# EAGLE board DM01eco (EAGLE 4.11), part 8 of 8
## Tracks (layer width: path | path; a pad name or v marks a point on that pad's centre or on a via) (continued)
N$57  (via drill 0.61) (continued)
  Route2 0.152: v266.06,171.45 v269.88,175.26
  Bottom 0.152: v269.88,175.26 268.61,176.53 268.61,177.16 B11.L2 | v266.06,171.45 266.06,170.18 v287.02,149.22 | v294.64,156.84 298.45,156.84 302.26,153.03 303.53,153.03 305.44,151.13 307.34,151.13 310.51,147.96 | 310.51,147.96 320.68,137.8 320.68,132.08 319.4,130.81 C07.D2 | 310.51,147.96 v311.15,148.59
N$58  (via drill 0.61)
  Top 0.152: v365.76,149.86 364.49,149.86 357.5,142.88 354.33,142.88 v348.62,137.16 | v299.72,206.38 296.55,203.2 291.46,208.28 288.29,208.28 281.94,201.93 276.86,201.93 271.78,196.85 271.78,194.31 B11.E2 | v317.5,184.15 317.5,184.78 318.13,185.42 320.68,185.42 321.94,186.69 B07.H2
  Route2 0.152: v306.07,160.66 306.07,161.93 320.68,176.53 320.68,185.42 321.94,186.69 B07.H2
  Route15 0.152: v299.72,206.38 318.13,187.96 318.13,186.06 316.87,184.78 v317.5,184.15
  Bottom 0.152: v365.76,149.86 382.27,133.35 382.27,130.81 C02.D2 | v348.62,137.16 344.81,133.35 339.73,138.43 332.74,138.43 329.56,141.61 327.02,141.61 325.75,142.88 321.31,142.88 315.6,148.59 313.69,148.59 310.51,151.77 310.51,154.31 311.79,155.58 306.7,160.66 v306.07,160.66
N$59  (via drill 0.61)
  Top 0.152: v266.06,184.15 267.97,186.06 267.97,189.87 B11.F2 | v297.81,153.03 304.8,160.02 304.8,161.29 307.98,164.47 307.98,170.18 321.94,184.15 323.21,182.88 321.94,181.61 B07.K2
  Route15 0.152: v266.06,184.15 266.06,182.88 295.91,153.03 v297.81,153.03 | C03.D2 369.57,130.81 369.57,133.35 365.12,137.8 365.12,139.06 358.14,146.05 353.06,146.05 346.71,152.4 346.71,154.31 346.07,154.94 346.07,159.39 342.9,162.56 342.9,163.19 332.74,173.36 332.74,174.62 331.47,175.9 330.2,175.9 326.39,179.71 323.21,179.71 322.58,180.34 B07.K2
N$60  (via drill 0.61)
  Route2 0.152: v298.45,168.28 300.36,168.28 303.53,165.1 304.8,166.37 305.44,166.37 311.15,172.09 311.15,172.72 314.96,176.53 316.23,176.53 v317.5,177.8
  Route15 0.152: B07.M2 322.58,173.99 322.58,170.81 333.38,160.02 333.38,154.31 337.19,150.5 341,150.5 346.71,144.78 346.71,143.51 356.24,133.98 356.24,131.44 356.87,130.81 C04.D2
  Bottom 0.152: v298.45,168.28 298.45,168.91 294.64,172.72 289.56,172.72 276.23,186.06 276.23,186.69 274.32,188.59 273.69,188.59 271.14,191.14 269.88,189.87 271.14,188.59 271.14,187.96 B11.H2 | v317.5,177.8 317.5,177.16 318.13,176.53 320.68,176.53 321.94,175.26 B07.M2
N$61  (via drill 0.61)
  Route2 0.152: v266.7,178.44 267.33,179.07 267.33,181.61 267.97,182.25 267.97,183.52 B11.J2 | v280.67,167 280.67,168.91 278.13,171.45 292.1,185.42 v297.18,185.42
  Route15 0.152: C05.D2 344.17,130.81 344.17,133.98 339.09,139.06 339.09,140.34 333.38,146.05 333.38,147.96 323.21,158.12 323.21,160.66 325.12,162.56 323.21,164.47 323.21,167 322.58,167.64 B07.P2 321.94,167.64 319.4,167.64 310.51,176.53 304.8,176.53 297.18,184.15 v297.18,185.42
  Bottom 0.152: v266.7,178.44 266.7,177.16 270.51,173.36 275.59,173.36 280.04,168.91 280.04,167.64 v280.67,167
N$62  (via drill 0.61)
  Top 0.152: v279.4,177.16 281.31,175.26 v295.91,189.87 | v334.64,142.24 333.38,140.97 333.38,135.89 332.11,134.62 332.11,130.81 C06.D2
  Route15 0.152: v334.64,142.24 334.64,144.15 332.74,146.05 332.74,147.96 322.58,158.12 322.58,161.29 B07.S2
  Bottom 0.152: v279.4,177.16 278.76,177.16 276.23,179.71 276.23,180.34 274.32,182.25 273.69,182.25 273.05,182.88 271.78,181.61 B11.K2 | v295.91,189.87 297.18,189.87 320.68,166.37 320.68,163.83 321.94,162.56 B07.S2
N$63  (via drill 0.61)
  Route2 0.152: v245.75,170.18 245.75,170.81 257.81,182.88 v258.44,182.88
  Route15 0.152: v258.44,182.88 259.71,182.88 263.52,179.07 | 263.52,179.07 264.8,179.07 267.33,176.53 269.88,176.53 271.14,175.26 B11.M2 | 263.52,179.07 300.99,141.61 304.17,141.61 312.42,133.35 309.88,130.81 306.7,130.81 C08.D2
  Bottom 0.152: v245.75,170.18 244.47,171.45 244.47,172.72 237.49,179.71 236.85,179.71 234.31,182.25 234.31,182.88 223.52,193.68 220.98,193.68 B15.E2
N$64  (via drill 0.61)
  Top 0.152: B06.J2 332.11,184.78 332.74,184.78 334.64,186.69 B06.H2
  Route2 0.152: v295.27,183.52 296.55,183.52 299.08,186.06 300.99,186.06 303.53,183.52 305.44,185.42 311.15,185.42 314.96,189.23 320.04,189.23 323.85,193.04 v323.85,193.68
  Route15 0.152: v323.85,193.68 325.75,193.68 328.93,190.5 329.56,190.5 330.83,189.23 333.38,189.23 334.64,187.96 B06.H2
  Bottom 0.152: v295.27,183.52 294.64,182.88 292.1,182.88 284.48,190.5 284.48,193.04 B10.E2
N$65  (via drill 0.61)
  Top 0.152: v290.83,191.14 287.65,187.96 284.48,187.96 B10.H2 | v315.6,166.37 323.21,166.37 v329.56,172.72
  Bottom 0.152: v290.83,191.14 290.83,190.5 314.96,166.37 v315.6,166.37 | v329.56,172.72 330.83,172.72 331.47,172.09 B06.N2 332.11,170.81 334.01,168.91 334.64,168.91 B06.P2
N$66  (via drill 0.61)
  Top 0.152: B23.V2 116.2,153.03 116.84,153.03 118.75,154.94 B23.U2 | v259.71,130.81 280.04,151.13 281.94,151.13 283.85,153.03 283.85,154.94 B10.U2
  Route2 0.152: v259.71,130.81 257.81,130.81 255.27,133.35 253.37,131.44 250.82,131.44 243.84,138.43 243.84,139.06 231.78,151.13 226.69,151.13 226.06,151.77 v218.44,144.15 | v205.1,149.86 180.97,149.86 174.62,143.51 158.75,143.51 156.84,141.61 155.57,141.61 148.59,134.62 139.7,134.62 138.43,135.89 v137.79,135.25
  Bottom 0.152: v218.44,144.15 217.81,144.15 215.9,146.05 214.63,146.05 214,146.69 208.28,146.69 v205.1,149.86 | v137.79,135.25 137.16,135.25 135.25,133.35 116.2,152.4 B23.V2
N$67  (via drill 0.61)
  Top 0.152: v301.62,147.32 306.07,151.77 B08.V2 306.7,153.03 308.61,154.94 309.25,154.94 B08.U2
  Bottom 0.152: v301.62,147.32 287.65,161.29 284.48,161.29 B10.S2
N$68  (via drill 0.61)
  Top 0.152: v287.65,169.55 287.02,168.91 284.48,168.91 B10.P2 | v294,161.93 302.26,170.18 305.44,170.18 306.07,170.81 B08.N2
  Bottom 0.152: v287.65,169.55 287.65,168.28 v294,161.93 | B08.P2 309.25,168.91 308.61,168.91 306.7,170.81 B08.N2
N$69
  Top 0.152: B08.H2 309.25,186.69 308.61,186.69 306.7,184.78 B08.J2
  Route2 0.152: B10.M2 284.48,175.26 287.65,175.26 290.19,177.8 291.46,177.8 292.74,179.07 297.18,179.07 299.08,180.97 300.36,180.97 302.26,182.88 305.44,182.88 306.07,183.52 B08.J2
N$70  (via drill 0.61)
  Top 0.152: v323.21,144.78 324.49,144.78 331.47,151.77 B06.V2 332.11,153.03 334.01,154.94 334.64,154.94 B06.U2
  Bottom 0.152: v323.21,144.78 287.65,180.34 284.48,180.34 B10.K2
N$71  (via drill 0.61)
  Top 0.152: v245.75,166.37 247.01,166.37 263.52,182.88 272.42,182.88 273.69,181.61 274.32,182.25 275.59,180.97 274.32,179.71 273.69,179.71 272.42,178.44 272.42,175.9 273.69,174.62 272.42,173.36 269.88,173.36 268.61,172.09 B11.N2
  Route2 0.152: v223.52,192.41 222.88,192.41 220.98,190.5 220.98,187.96 B15.H2 | v300.36,134.62 296.55,130.81 294,130.81 C09.D2
  Route15 0.152: v300.36,134.62 299.72,133.98 285.75,147.96 285.75,148.59 285.12,149.22 285.12,151.13 269.24,167 269.24,170.18 268.61,170.81 B11.N2
  Bottom 0.152: v223.52,192.41 222.88,192.41 220.98,190.5 245.11,166.37 v245.75,166.37
N$72  (via drill 0.61)
  Top 0.152: v252.73,153.67 253.37,153.67 258.44,158.75 258.44,159.39 262.25,163.19 262.89,163.19 267.33,167.64 267.33,168.91 v267.97,169.55
  Route2 0.152: v295.91,142.24 284.48,130.81 281.31,130.81 C10.D2
  Bottom 0.152: v252.73,153.67 251.46,153.67 234.95,170.18 234.95,170.81 226.69,179.07 226.06,179.07 224.79,180.34 220.98,180.34 B15.K2 | v267.97,169.55 270.51,169.55 271.14,168.91 B11.P2 271.78,167.64 272.42,167 272.42,164.47 286.38,150.5 287.02,150.5 295.27,142.24 v295.91,142.24
N$73  (via drill 0.61)
  Top 0.152: v226.69,177.8 223.52,174.62 220.98,174.62 B15.M2 | v272.42,135.89 271.78,135.89 269.88,133.98 269.88,132.08 268.61,130.81 C11.D2 | v274.32,160.66 275.59,160.66 277.5,158.75 v264.16,145.41
  Route15 0.152: v274.32,160.66 274.32,161.29 271.14,164.47 268.61,164.47 B11.R2
  Bottom 0.152: v226.69,177.8 252.09,152.4 253.37,152.4 254.63,151.13 257.18,151.13 263.52,144.78 | 263.52,144.78 v272.42,135.89 | 263.52,144.78 v264.16,145.41
N$74  (via drill 0.61)
  Top 0.152: v254,136.53 254,139.06 254.63,139.7 254.63,142.24 256.54,144.15 | 256.54,144.15 269.88,157.48 269.88,160.02 271.14,161.29 B11.S2 | 256.54,144.15 v255.27,145.41
  Route2 0.152: v227.97,171.45 227.33,170.81 226.06,170.81 224.16,168.91 220.98,168.91 B15.P2
  Bottom 0.152: v254,136.53 254,135.89 255.27,134.62 255.27,130.81 C12.D2 | v227.97,171.45 227.97,170.81 235.59,163.19 236.22,163.19 238.12,161.29 238.12,160.66 248.28,150.5 250.19,150.5 v255.27,145.41
N$75  (via drill 0.61)
  Top 0.152: v249.56,134.62 245.75,130.81 243.21,130.81 C13.D2 | v223.52,163.19 221.62,163.19 220.98,162.56 B15.S2 | v261.62,156.84 257.81,156.84 250.82,149.86 247.01,149.86 v243.21,146.05
  Bottom 0.152: v249.56,134.62 248.28,134.62 236.22,146.69 | 236.22,146.69 232.41,150.5 232.41,153.67 223.52,162.56 v223.52,163.19 | v261.62,156.84 262.25,156.21 264.16,158.12 267.97,158.12 B11.T2 | v243.21,146.05 240.66,146.05 240.03,146.69 236.22,146.69
N$76  (via drill 0.61)
  Top 0.152: v256.54,139.7 267.97,151.13 269.24,151.13 271.14,153.03 271.14,154.94 B11.U2 | v244.47,152.4 244.47,151.77 243.84,151.13 241.3,151.13 v232.41,142.24
  Route2 0.152: v232.41,142.24 231.78,141.61 231.78,135.89 230.5,134.62 230.5,130.81 C14.D2
  Bottom 0.152: v232.41,142.24 231.78,142.24 223.52,150.5 222.88,150.5 221.62,151.77 221.62,154.31 220.98,154.94 B15.U2 | v256.54,139.7 256.54,140.34 v244.47,152.4
N$77  (via drill 0.61)
  Top 0.152: 224.79,141.61 225.43,141.61 233.68,149.86 v233.68,150.5 | 224.79,141.61 223.52,141.61 222.25,140.34 222.25,139.06 220.34,137.16 222.25,135.25 222.25,132.72 220.34,130.81 217.81,130.81 C15.D2 | v241.3,147.96 241.94,147.96 254,160.02 255.27,160.02 v255.91,160.66 | v100.97,203.84 93.98,196.85 93.98,194.31 B25.E2 | v130.18,168.28 v130.18,162.56 | v150.5,141.61 156.84,141.61 165.1,149.86 166.37,149.86 168.28,151.77 170.81,151.77 175.9,146.69 186.06,156.84 186.69,156.84 195.58,165.74 v196.22,165.74 | v224.79,140.34 224.79,141.61
  Route2 0.152: v233.68,150.5 238.76,145.41 v241.3,147.96
  Route15 0.152: v196.22,165.74 195.58,165.1 207.01,153.67 207.01,152.4 209.55,149.86 210.82,149.86 215.26,145.41 219.71,145.41 v224.79,140.34
  Bottom 0.152: v255.91,160.66 256.54,160.66 263.52,153.67 267.33,153.67 267.97,153.03 B11.V2 | v100.97,203.84 100.97,202.56 108.58,194.94 108.58,194.31 130.18,172.72 v130.18,168.28 | v130.18,162.56 130.18,160.66 139.7,151.13 140.97,151.13 v150.5,141.61
N$78  (via drill 0.61)
  Top 0.152: B25.H2 93.98,187.96 97.16,187.96 102.23,193.04 102.23,195.58 102.87,196.22 B24.D2 | v170.18,166.37 167.64,163.83 162.56,163.83 161.93,163.19 161.93,162.56 160.02,160.66 159.38,160.66 158.12,159.39 158.12,156.84 159.38,155.58 154.94,151.13 151.13,151.13 143.51,143.51 142.24,143.51 138.43,147.32 v134.62,143.51
  Route15 0.152: v170.18,166.37 170.81,165.74 170.81,164.47 194.31,140.97 196.85,140.97 204.47,133.35 204.47,130.81 C16.D2 | v134.62,143.51 94.61,183.52 94.61,186.06 93.98,186.69 B25.H2
N$79  (via drill 0.61)
  Top 0.152: B25.K2 93.98,181.61 97.16,181.61 104.78,189.23 104.78,191.77 106.05,193.04 B24.E2 | v175.9,122.56 175.9,123.19 179.71,127 180.34,127 181.61,128.27 182.25,128.27 183.51,129.54 187.96,125.09 189.87,125.09 191.77,127 191.77,129.54 C17.D2
  Route15 0.152: v175.9,122.56 175.9,123.83 173.99,125.73 173.35,125.73 172.09,127 172.09,128.27 161.29,139.06 161.29,140.34 160.02,141.61 160.02,142.88 155.57,147.32 155.57,148.59 152.4,151.77 152.4,154.31 153.67,155.58 148.59,160.66 142.24,160.66 110.49,192.41 107.31,192.41 106.68,193.04 B24.E2
N$80  (via drill 0.61)
  Top 0.152: B25.M2 93.98,175.26 93.98,176.53 94.61,177.16 94.61,178.44 105.41,189.23 105.41,190.5 107.95,193.04 107.95,194.94 106.68,196.22 104.78,194.31 104.78,192.41 103.5,191.14 B24.F2 | v152.4,160.02 151.76,160.02 v144.15,152.4
  Route15 0.152: v144.15,152.4 120.65,175.9 118.75,175.9 117.47,177.16 117.47,179.07 110.49,186.06 105.41,186.06 104.78,186.69 104.78,188.59 103.5,189.87 B24.F2
  Bottom 0.152: v152.4,160.02 155.57,160.02 161.93,153.67 161.93,153.03 173.99,140.97 173.99,139.06 179.07,133.98 179.07,130.81 C18.D2
N$81  (via drill 0.61)
  Top 0.152: v109.86,181.61 97.16,168.91 93.98,168.91 B25.P2
  Route15 0.152: v109.86,181.61 109.86,180.97 147.96,142.88 150.5,142.88 162.56,130.81 166.37,130.81 C19.D2
  Bottom 0.152: v109.86,181.61 109.22,181.61 107.31,183.52 107.31,184.15 107.95,184.78 106.05,186.69 B24.H2
N$82  (via drill 0.61)
  Top 0.152: v109.22,187.33 108.58,187.33 107.31,186.06 104.78,186.06 103.5,184.78 B24.J2 | v106.05,163.83 106.05,164.47 v118.75,177.16
  Route2 0.152: v106.05,163.83 99.06,163.83 97.16,161.93 93.98,161.93 B25.S2
  Bottom 0.152: 118.75,177.8 v109.22,187.33 | 118.75,177.8 142.88,153.67 142.88,152.4 155.57,139.7 155.57,138.43 156.84,137.16 154.31,134.62 154.31,130.81 C20.D2 | v118.75,177.16 118.75,177.8
N$83
  Route2 0.152: B25.U2 93.34,156.21 93.34,160.02 88.27,165.1 89.53,166.37 94.61,166.37 104.78,176.53 104.78,179.07 106.05,180.34 B24.K2
  Bottom 0.152: C21.D2 140.97,130.81 140.97,133.98 135.89,139.06 135.89,147.32 129.54,153.67 129.54,154.94 111.12,173.36 111.12,173.99 109.22,175.9 108.58,175.9 107.31,177.16 107.31,179.71 106.68,180.34 B24.K2
N$84  (via drill 0.61)
  Top 0.152: v133.35,143.51 130.18,140.34 130.18,135.25 121.92,127 123.83,125.09 126.36,125.09 128.27,127 128.27,129.54 C22.D2
  Bottom 0.152: 99.06,179.07 102.23,179.07 102.87,178.44 B24.L2 | 99.06,179.07 98.42,179.07 84.45,193.04 81.28,193.04 B26.E2 | v133.35,143.51 133.35,144.78 99.06,179.07
N$85  (via drill 0.61)
  Top 0.152: v92.08,196.22 92.08,195.58 87,190.5 85.09,192.41 83.19,192.41 81.28,190.5 81.28,187.96 B26.H2 | v100.97,170.18 100.97,171.45 102.23,172.72 104.78,172.72 106.05,173.99 B24.M2
  Route2 0.152: v121.28,139.7 116.2,134.62 116.2,130.81 C23.D2
  Bottom 0.152: v92.08,196.22 90.81,194.94 90.81,194.31 95.25,189.87 95.25,189.23 102.87,181.61 103.5,181.61 104.78,180.34 104.78,176.53 106.05,175.26 B24.M2 | v121.28,139.7 121.28,144.15 110.49,154.94 110.49,156.84 112.39,158.75 v100.97,170.18
N$86  (via drill 0.61)
  Top 0.152: v120.02,151.77 114.94,146.69 114.94,139.06 106.68,130.81 103.5,130.81 C24.D2 | v79.38,187.96 75.56,184.15 78.11,181.61 80.64,181.61 B26.K2
  Bottom 0.152: v120.02,151.77 104.78,167 104.78,169.55 103.5,170.81 B24.N2 102.87,172.09 102.23,172.72 99.06,172.72 93.34,178.44 92.71,178.44 81.28,189.87 v79.38,187.96
N$87  (via drill 0.61)
  Top 0.152: v110.49,147.32 93.98,130.81 90.81,130.81 C25.D2 | v104.78,157.48 104.78,163.83 106.05,165.1 105.41,165.74 105.41,166.37 106.05,167 106.05,167.64 B24.P2
  Bottom 0.152: 104.78,153.03 104.14,153.67 99.06,153.67 97.79,154.94 97.79,155.58 96.52,156.84 95.89,156.84 81.92,170.81 81.92,173.36 81.28,173.99 B26.M2 | 104.78,153.03 v110.49,147.32 | v104.78,157.48 104.78,153.03
N$88  (via drill 0.61)
  Top 0.152: C26.D2 78.11,130.81 80.64,130.81 82.55,132.72 82.55,135.25 81.28,136.53 86.36,141.61 86.36,144.15 88.27,146.05 88.27,147.32 v96.52,155.58 102.23,161.29 102.23,163.83 102.87,164.47 B24.R2
  Bottom 0.152: v96.52,155.58 84.45,167.64 81.28,167.64 B26.P2
N$89
  Route2 0.152: 69.85,147.96 79.38,157.48 79.38,160.02 80.64,161.29 B26.S2 | 69.85,147.96 66.67,144.78 66.67,135.89 65.41,134.62 65.41,130.81 C27.D2 | 69.85,147.96 88.9,147.96 95.25,154.31 96.52,154.31 97.79,155.58 97.79,156.21 102.87,161.29 106.05,161.29 B24.S2
N$90  (via drill 0.61)
  Top 0.152: C28.D2 52.7,130.81 56.52,130.81 71.75,146.05 73.66,146.05 79.38,151.77 79.38,153.67 80.64,154.94 B26.U2 81.28,156.21 81.92,156.84 85.09,156.84 93.34,165.1 v95.25,163.19
  Bottom 0.152: v95.25,163.19 99.06,159.39 102.87,159.39 B24.T2
N$91  (via drill 0.61)
  Top 0.152: v1.91,167.64 4.45,167.64 B32.P2 | v91.44,147.96 96.52,147.96 103.5,154.94 106.05,154.94 B24.U2 | v77.47,161.93 66.67,151.13 65.41,151.13 59.69,145.41 58.42,145.41 45.72,132.72 44.45,132.72 43.81,132.08 41.27,132.08 40.01,130.81 C29.D2
  Bottom 0.152: v1.91,167.64 22.23,147.32 22.23,146.05 28.57,139.7 28.57,132.72 29.21,132.08 34.29,132.08 35.56,130.81 39.37,130.81 C29.D2 | v77.47,161.93 v91.44,147.96
N$92  (via drill 0.61)
  Top 0.152: v68.58,170.81 67.31,170.81 46.99,150.5 35.56,150.5 v29.84,144.78 | v22.23,149.86 22.23,147.32 v19.68,144.78
  Route15 0.152: v19.68,144.78 21.59,142.88 21.59,139.06 26.67,133.98 26.67,130.81 C30.D2
  Bottom 0.152: v19.68,144.78 19.05,144.78 5.71,158.12 5.71,160.66 5.08,161.29 B32.S2 | v68.58,170.81 76.2,163.19 77.47,163.19 78.74,161.93 78.74,161.29 87.63,152.4 88.27,152.4 97.16,143.51 100.97,143.51 104.78,147.32 104.78,148.59 103.5,149.86 103.5,151.77 B24.V2 | v29.84,144.78 27.3,144.78 v22.23,149.86
POWER_CLEAR  (via drill 0.61)
  Top 0.152: v40.64,218.44 29.84,207.65 28.57,207.65 5.08,184.15 5.08,181.61 B32.K2 | v146.69,280.03 170.81,280.03 177.8,287.02 v208.28,287.02 | v259.08,283.21 274.32,283.21 274.95,283.84 316.87,283.84 317.5,284.48 328.93,273.05 330.2,274.32 335.92,274.32 340.36,278.76 356.24,278.76 356.87,279.4 386.08,279.4 405.13,260.35 402.59,257.81 402.59,256.54 405.13,254 398.14,247.02 398.14,246.38 396.88,245.11 396.88,239.4 384.18,226.69 384.18,224.16 382.9,222.89 A02.V2 382.27,221.62 368.94,208.28 368.94,205.74 364.49,201.3 363.22,201.3 361.95,200.03 361.95,199.39 356.87,194.31 v356.24,194.31 | v358.77,48.26 356.87,50.16 386.71,80.01 v387.35,80.01 | v363.86,113.03 363.86,114.94 365.76,116.84 365.76,118.11 360.05,123.83 367.67,131.44 368.94,131.44 v372.75,135.25
  Route2 0.152: v40.64,218.44 40.64,219.71 48.26,227.33 54.61,227.33 86.36,259.08 92.71,259.08 99.06,265.43 105.41,265.43 117.47,277.5 120.02,277.5 121.92,279.4 123.83,279.4 124.46,280.03 v146.69,280.03 | v372.75,135.25 372.75,135.89 375.29,138.43 375.29,144.15 375.92,144.78 375.92,147.96 384.81,156.84 386.71,156.84 388.62,154.94 v388.62,154.31
  Route15 0.152: v208.28,287.02 208.91,287.02 210.82,285.11 245.75,285.11 247.01,283.84 258.44,283.84 v259.08,283.21 | v387.35,80.01 387.35,83.19 381,89.54 381,90.17 374.65,96.52 374.65,97.79 371.48,100.97 371.48,106.05 364.49,113.03 v363.86,113.03
  Bottom 0.152: v358.77,48.26 358.77,43.18 382.27,19.69 382.27,16.51 D02.V2 | v388.62,154.31 388.62,155.58 374.01,170.18 373.38,170.18 372.11,171.45 375.29,174.62 368.3,181.61 368.3,182.25 v356.24,194.31
RUN  (via drill 0.61)
  Top 0.152: v284.48,75.57 286.38,75.57 302.26,91.44 303.53,91.44 v304.8,92.71 | v311.15,191.77 311.15,192.41 323.85,205.11 323.85,207.01 v334.64,217.81
  Route2 0.152: v298.45,101.6 298.45,103.51 297.18,104.78 327.66,135.25 332.74,135.25 v346.71,149.22
  Route15 0.152: v284.48,75.57 288.29,71.75 291.46,71.75 334.64,28.58 334.64,26.04 D06.S2 | v346.71,149.22 346.71,151.77 346.07,152.4 346.07,154.31 310.51,189.87 310.51,191.14 v311.15,191.77 | v334.64,217.81 334.64,221.62 338.45,225.43 335.92,227.97 335.92,230.5 335.28,231.14 A06.S2
  Bottom 0.152: v304.8,92.71 306.7,94.62 299.72,101.6 v298.45,101.6
T2  (via drill 0.61)
  Top 0.152: v399.42,41.91 382.9,25.4 382.9,22.86 D02.T2 | v402.59,89.54 v382.9,69.85 | v375.92,121.92 377.19,121.92 394.33,139.06 394.33,143.51 v401.32,150.5 | v377.19,174.62 377.19,175.26 384.81,182.88 385.44,182.88 387.35,184.78 387.35,185.42 v395.61,193.68 | v372.75,217.81 374.65,217.81 381.63,224.79 381.63,227.33 382.27,227.97 A02.T2 382.9,229.24 384.18,230.5 384.18,232.41 384.81,233.05 389.89,233.05 391.8,234.95 v391.8,236.22 | v151.76,220.98 158.75,220.98 160.02,219.71 160.66,220.34 161.29,220.34 177.8,236.86 177.8,237.49 186.06,245.75 186.69,245.75 198.75,257.81 199.39,257.81 203.2,261.62 v207.65,261.62
  Route2 0.152: v30.48,129.54 30.48,130.18 41.27,140.97 44.45,140.97 73.66,170.18 78.74,170.18 84.45,175.9 85.72,175.9 111.76,201.93 117.47,201.93 124.46,208.91 125.73,208.91 143.51,226.69 v147.32,226.69 | v231.78,243.21 234.31,243.21 236.85,245.75 238.12,245.75 251.46,259.08 257.18,259.08 273.05,274.95 275.59,274.95 277.5,273.05 284.48,280.03 284.48,280.67 v293.37,289.56
  Bottom 0.152: v399.42,41.91 405.13,47.62 v382.9,69.85 | v402.59,89.54 405.13,92.08 381,116.21 381,117.48 379.73,118.75 378.46,118.75 375.92,121.29 v375.92,121.92 | v401.32,150.5 400.69,150.5 377.19,173.99 v377.19,174.62 | v395.61,193.68 384.18,205.11 384.18,206.38 v372.75,217.81 | v30.48,129.54 23.5,136.53 21.59,134.62 19.68,134.62 17.78,136.53 19.05,137.8 19.05,140.34 8.89,150.5 6.99,150.5 5.08,152.4 5.08,154.94 B32.U2 | v147.32,226.69 147.32,225.43 v151.76,220.98 | v207.65,261.62 207.65,260.99 213.36,255.27 219.71,255.27 v231.78,243.21 | v293.37,289.56 350.52,289.56 378.46,261.62 383.54,261.62 384.18,260.99 384.18,255.27 394.33,245.11 394.33,242.57 393.06,241.3 394.33,240.03 394.33,237.49 392.43,235.59 v391.8,236.22
VCC  (via drill 0.61)
  Top 0.508: C32.A2 5.08,140.34 8.89,140.34 10.16,141.61 15.88,141.61 17.14,140.34 C31.A2 17.78,140.34 26.67,149.22 | v35.56,144.15 31.75,140.34 30.48,140.34 C30.A2 | 26.67,149.22 27.3,149.86 29.84,149.86 v30.48,150.5 | 48.9,130.18 53.98,135.25 53.98,137.8 55.24,139.06 C28.A2 | 48.9,130.18 41.27,122.56 41.27,116.21 12.7,87.63 12.7,75.57 7.62,70.48 5.08,70.48 D32.A2 | 48.9,130.18 57.15,121.92 59.69,121.92 74.3,136.53 71.12,139.7 68.58,139.7 C27.A2 | v363.22,142.88 360.68,140.34 C04.A2 | v382.9,142.24 379.1,146.05 373.38,140.34 C03.A2 | v391.8,146.05 386.08,140.34 C02.A2 | v302.89,144.78 298.45,140.34 297.18,140.34 C09.A2 | v314.32,145.41 314.32,144.78 309.88,140.34 C08.A2 | v332.11,142.88 325.12,142.88 322.58,140.34 C07.A2 | v341.63,145.41 335.28,139.06 C06.A2 | v352.43,143.51 351.15,143.51 347.98,140.34 C05.A2 | v125.73,146.05 120.02,140.34 119.38,140.34 C23.A2 | C22.A2 132.08,140.34 133.99,142.24 135.89,142.24 139.06,145.41 144.15,140.34 C21.A2 144.78,140.34 v150.5,146.05 | v111.76,146.05 106.68,140.97 106.68,140.34 C24.A2 | v239.4,144.78 234.95,140.34 233.68,140.34 C14.A2 | v269.88,142.88 264.8,142.88 263.52,141.61 260.35,141.61 259.08,140.34 C12.A2 | v278.13,144.15 275.59,144.15 271.78,140.34 C11.A2 | v162.56,145.41 157.48,140.34 C20.A2 | v187.32,142.88 184.78,140.34 182.88,140.34 C18.A2 | v210.19,144.78 208.28,142.88 208.28,140.34 C16.A2 | v201.29,146.05 195.58,140.34 C17.A2 | v182.25,151.13 171.45,140.34 170.18,140.34 C19.A2 | v227.33,145.41 226.06,145.41 220.98,140.34 C15.A2 | v86.36,145.41 81.28,140.34 C26.A2 | v125.09,210.82 121.28,207.01 119.38,207.01 B23.A2 | v175.9,210.19 173.35,210.19 170.18,207.01 B19.A2
  Top 0.508: v137.79,212.09 132.72,207.01 132.08,207.01 B22.A2 | v189.87,212.72 188.59,212.72 182.88,207.01 B18.A2 | v27.3,208.91 19.68,208.91 17.78,207.01 B31.A2 | v36.83,201.93 40.64,201.93 42.55,203.84 42.55,205.74 B29.A2 43.18,207.01 46.35,210.19 v48.9,210.19 | v59.69,209.55 58.42,209.55 55.88,207.01 B28.A2 | v76.2,210.82 72.39,210.82 68.58,207.01 B27.A2 | v86.36,212.72 86.36,212.09 81.28,207.01 B26.A2 | v109.22,208.28 107.95,208.28 106.68,207.01 B24.A2 | 369.57,211.46 v375.29,217.17 | 369.57,211.46 367.03,208.91 363.22,208.91 361.31,207.01 360.68,207.01 B04.A2 | 369.57,211.46 v367.67,211.46 | v393.06,211.46 390.52,211.46 386.08,207.01 B02.A2 | B06.A2 335.28,207.01 337.19,207.01 338.45,208.28 346.07,208.28 347.35,207.01 B05.A2 347.98,207.01 v353.69,212.72 | B10.A2 284.48,207.01 285.75,207.01 287.65,208.91 292.74,208.91 295.91,205.74 296.55,206.38 B09.A2 297.18,206.38 303.53,212.72 309.25,207.01 B08.A2 309.88,207.01 312.42,207.01 v317.5,212.09 | v328.3,212.72 322.58,207.01 B07.A2 | v252.09,282.57 246.38,276.86 A13.A2 | v213.36,282.57 208.28,277.5 208.28,276.86 A16.A2 | A14.A2 233.04,276.86 229.87,276.86 226.69,280.03 224.16,280.03 220.98,276.86 A15.A2 | v265.43,210.82 264.16,209.55 261.62,209.55 259.08,207.01 B12.A2 | v243.21,208.28 238.76,208.28 237.49,207.01 233.68,207.01 B14.A2 | v142.88,288.92 132.08,278.13 132.08,276.86 A22.A2 | A19.A2 170.18,276.86 173.99,276.86 175.26,278.13 180.97,278.13 182.25,276.86 A18.A2 | v203.2,281.3 201.93,281.3 198.12,277.5 196.22,277.5 195.58,276.86 A17.A2 | v278.76,212.09 276.86,212.09 271.78,207.01 B11.A2 | v215.26,212.09 215.26,211.46 210.82,207.01 208.28,207.01 B16.A2
  Top 0.508: 26.67,149.22 20.32,155.58 60.96,196.22 v60.96,197.49
  Route2 0.508: C29.A2 43.18,140.34 46.99,140.34 48.26,141.61 54.61,141.61 55.88,140.34 C28.A2 | v332.11,142.88 334.64,140.34 C06.A2 | v96.52,142.88 93.98,140.34 C25.A2 | v302.89,144.78 288.93,144.78 284.48,140.34 C10.A2 | v225.43,210.82 221.62,207.01 220.98,207.01 B15.A2
  Route15 0.508: v393.06,211.46 397.51,207.01 398.14,207.01 B01.A2 | v353.69,212.72 359.41,207.01 360.05,207.01 B04.A2 | A13.A2 245.75,275.59 242.57,275.59 240.03,273.05 238.12,274.95 234.31,274.95 233.68,275.59 A14.A2
  Bottom 0.508: 36.2,144.15 38.73,144.15 42.55,140.34 C29.A2 | 36.2,144.15 v35.56,144.15 | v30.48,150.5 30.48,149.86 36.2,144.15 | C27.A2 68.58,140.34 74.3,146.05 80.64,139.7 C26.A2 | v363.22,142.88 369.57,142.88 372.75,139.7 C03.A2 | v382.9,142.24 384.81,140.34 385.44,140.34 C02.A2 | v391.8,146.05 397.51,140.34 398.14,140.34 C01.A2 | v302.89,144.78 304.17,144.78 309.25,139.7 C08.A2 | v314.32,145.41 319.4,140.34 321.94,140.34 C07.A2 | v341.63,145.41 346.71,140.34 347.35,140.34 C05.A2 | v352.43,143.51 353.06,142.88 356.24,142.88 358.77,140.34 360.05,140.34 C04.A2 | v96.52,142.88 103.5,142.88 106.05,140.34 C24.A2 | v125.73,146.05 131.44,140.34 C22.A2 | v111.76,146.05 113.03,146.05 118.75,140.34 C23.A2 | v239.4,144.78 241.3,144.78 245.75,140.34 C13.A2 246.38,139.06 247.01,138.43 250.19,138.43 250.82,137.8 257.18,137.8 258.44,139.06 C12.A2 | v269.88,142.88 271.14,141.61 271.14,140.34 C11.A2 | v278.13,144.15 281.94,140.34 283.85,140.34 C10.A2 | v162.56,145.41 164.47,145.41 169.54,140.34 C19.A2 | 187.96,142.88 192.41,142.88 194.94,140.34 C17.A2 | 187.96,142.88 v187.32,142.88 | v210.19,144.78 215.9,144.78 220.34,140.34 C15.A2 | v201.29,146.05 207.65,139.7 C16.A2 | v182.25,151.13 182.25,148.59 187.96,142.88 | v227.33,145.41 232.41,140.34 233.04,140.34 C14.A2 | v150.5,146.05 151.13,146.05 156.84,140.34 C20.A2 | v86.36,145.41 88.27,145.41 93.34,140.34 C25.A2 | B16.A2 207.65,206.38 201.29,212.72 195.58,207.01 B17.A2 194.94,207.01 194.94,207.65 v189.87,212.72 | v125.09,210.82 127.64,210.82 131.44,207.01 B22.A2 | B19.A2 169.54,207.01 165.74,207.01 164.47,208.28 161.93,208.28 158.75,205.11 157.48,206.38 B20.A2 156.84,205.74 151.13,211.46 146.69,207.01 144.78,207.01 B21.A2 144.15,207.01 139.06,212.09 v137.79,212.09
  Bottom 0.508: v175.9,210.19 179.07,207.01 182.25,207.01 B18.A2 | B25.A2 93.34,207.01 92.08,207.01 v86.36,212.72 86.36,214.63 93.34,221.62 99.69,215.27 99.69,212.72 106.05,206.38 B24.A2 | B32.A2 5.08,207.01 6.99,207.01 10.16,210.19 13.97,210.19 17.14,207.01 B31.A2 | v27.3,208.91 29.21,207.01 29.84,207.01 B30.A2 30.48,205.74 31.11,205.11 31.11,202.56 32.38,201.3 33.02,201.3 33.66,200.66 34.92,201.93 v36.83,201.93 | 52.07,207.01 55.24,207.01 B28.A2 | 52.07,207.01 v48.9,210.19 | v59.69,209.55 62.87,209.55 65.41,207.01 67.94,207.01 B27.A2 | v76.2,210.82 80.01,207.01 80.64,207.01 B26.A2 | v109.22,208.28 113.67,208.28 114.94,207.01 118.75,207.01 B23.A2 | v375.29,217.17 385.44,207.01 B02.A2 | v367.67,211.46 372.11,207.01 372.75,207.01 B03.A2 | v317.5,212.09 321.94,207.65 321.94,207.01 B07.A2 | v328.3,212.72 334.01,207.01 334.64,207.01 B06.A2 | v252.09,282.57 258.44,276.22 A12.A2 | v213.36,282.57 214,282.57 220.34,276.22 A15.A2 | B14.A2 233.04,206.38 228.6,210.82 v225.43,210.82 225.43,212.72 219.71,218.44 219.71,223.52 170.81,272.41 170.81,274.95 170.18,275.59 A19.A2 | B12.A2 258.44,206.38 252.09,212.72 246.38,207.01 B13.A2 245.75,207.01 244.47,208.28 v243.21,208.28 | v265.43,210.82 269.24,207.01 271.14,207.01 B11.A2 | v142.88,288.92 144.78,288.92 146.69,290.83 149.22,290.83 151.76,288.29 170.81,288.29 180.97,278.13 | 180.97,278.13 182.25,276.86 A18.A2 | 180.97,278.13 189.87,278.13 191.13,276.86 194.94,276.86 A17.A2 | v203.2,281.3 207.65,276.86 A16.A2 | v278.76,212.09 283.85,207.01 B10.A2 | v215.26,212.09 220.34,207.01 B15.A2 | v60.96,197.49 60.96,198.12 52.07,207.01
WCOV  (via drill 0.61)
  Top 0.152: 200.66,246.38 195.58,241.3 | 195.58,241.3 193.68,239.4 193.68,234.31 191.13,231.78 192.41,230.5 193.04,231.14 194.94,231.14 A17.S2 | 200.66,246.38 203.84,246.38 204.47,247.02 A16.L2 | v267.33,224.16 280.67,237.49 283.85,237.49 A10.P2 | v223.52,264.8 219.07,264.8 215.26,260.99 | 215.26,260.99 200.66,246.38 | 215.26,260.99 v215.9,260.35 | 195.58,241.3 v196.22,241.3
  Bottom 0.152: 196.22,240.66 193.68,243.21 193.68,245.75 192.41,247.02 A17.L2 | 196.22,240.66 200.66,236.22 205.74,236.22 207.65,234.31 207.65,232.41 A16.S2 | 193.68,261.62 187.96,261.62 186.69,262.89 182.88,262.89 A18.E2 | 193.68,261.62 194.94,262.89 A17.E2 | v267.33,224.16 265.43,222.25 223.52,264.16 v223.52,264.8 | v215.9,260.35 214.63,261.62 213.36,261.62 212.09,262.89 208.28,262.89 A16.E2 | 193.68,261.62 193.68,255.91 200.66,248.92 203.84,248.92 204.47,248.28 A16.L2 | v196.22,241.3 196.22,240.66
WCOV0  (via drill 0.61)
  Top 0.152: v26.67,156.84 27.3,156.84 29.21,158.75 29.84,158.75 39.37,168.28 39.37,170.81 B29.N2 | v127.64,78.11 v118.11,78.11 | v222.25,1.91 227.33,1.91 v241.3,15.88 | v247.65,8.89 254.63,8.89 256.54,10.79 266.7,10.79 279.4,23.5 279.4,24.77 282.57,27.94 282.57,29.84 283.85,31.12 D10.P2
  Route15 0.152: v26.67,156.84 27.3,156.84 29.84,159.39 38.1,151.13 40.64,151.13 99.06,92.71 99.06,92.08 100.33,90.81 101.6,90.81 108.58,83.82 112.39,83.82 v118.11,78.11 | v173.35,36.83 173.99,36.83 177.8,33.02 184.15,33.02 200.03,17.14 205.74,17.14 214.63,8.26 215.9,8.26 v222.25,1.91
  Bottom 0.152: v127.64,78.11 132.72,78.11 155.57,55.24 155.57,49.53 165.1,40.01 170.18,40.01 v173.35,36.83 | v241.3,15.88 241.3,15.24 v247.65,8.89
WCOV1  (via drill 0.61)
  Top 0.152: v120.02,1.91 140.97,1.91 142.88,3.81 144.15,3.81 v155.57,15.24 | v162.56,6.99 164.47,6.99 v170.81,13.34
  Route2 0.152: v5.71,104.78 5.71,105.41 28.57,128.27 28.57,134.62 34.29,140.34 34.29,145.41 37.47,148.59 38.1,148.59 42.55,153.03 42.55,154.94 B29.U2 | v170.81,13.34 187.32,13.34 191.13,17.14 196.85,17.14 200.66,20.95 202.56,20.95 207.65,15.88 219.07,27.3 219.07,29.84 220.34,31.12 D15.P2
  Route15 0.152: v5.71,104.78 5.71,103.51 67.94,41.27 67.94,40.64 69.22,39.37 70.48,39.37 86.36,23.5 92.71,23.5 99.06,17.14 104.78,17.14 v120.02,1.91
  Bottom 0.152: v155.57,15.24 155.57,13.97 v162.56,6.99
WCOV2  (via drill 0.61)
  Top 0.152: v120.02,99.06 120.02,99.7 127.64,107.32 127.64,108.59 128.91,109.86 129.54,109.86 133.35,113.67 133.35,116.84 132.08,118.11 149.86,135.89 149.86,137.8 146.69,140.97 151.76,146.05 151.76,147.32 v165.74,161.29
  Route2 0.152: v119.38,83.19 119.38,85.09 113.03,91.44 116.2,94.62 116.2,95.25 v120.02,99.06 | v165.74,161.29 165.74,162.56 156.84,171.45 162.56,177.16 162.56,178.44 160.02,180.97 168.28,189.23 168.28,194.94 195.58,222.25 195.58,222.89 206.38,233.68 206.38,239.4 215.9,248.92 222.25,248.92 228.6,255.27 231.78,255.27 233.04,256.54 A14.H2
  Route15 0.152: v119.38,83.19 131.44,71.12 133.35,71.12 139.06,65.41 140.34,65.41 141.6,64.14 141.6,63.5 163.83,41.27 157.48,34.92 157.48,32.38 D20.P2
WCOV3  (via drill 0.61)
  Top 0.152: v107.95,44.45 107.95,43.18 97.16,32.38 93.98,32.38 D25.P2 | v182.88,160.02 183.51,160.02 191.13,167.64 191.13,169.55 189.23,171.45 224.16,206.38 v224.79,206.38
  Route2 0.152: v107.95,44.45 107.95,46.99 106.68,48.26 117.47,59.05 117.47,64.77 124.46,71.75 128.91,71.75 135.25,78.11 136.53,78.11 146.69,88.27 148.59,88.27 154.31,82.55 165.1,93.34 166.37,93.34 168.28,95.25 168.28,96.52 168.91,97.16 168.91,100.33 163.83,105.41 168.28,109.86 168.28,116.21 v197.49,145.41 | v215.9,214.63 215.9,217.81 231.78,233.68 231.78,234.95 233.68,236.86 234.31,236.86 234.95,237.49 v234.95,238.12
  Route15 0.152: v224.79,206.38 216.53,214.63 v215.9,214.63
  Bottom 0.152: v197.49,145.41 196.22,145.41 183.51,158.12 183.51,159.39 v182.88,160.02 | v234.95,238.12 234.95,238.76 234.31,239.4 231.78,239.4 230.5,240.66 A14.N2
WCOV4  (via drill 0.61)
  Top 0.152: v19.68,62.23 14.61,57.15 31.75,40.01 31.75,37.47 30.48,36.2 30.48,32.38 D30.P2 | v160.66,226.69 161.29,226.69 v195.58,260.99
  Route2 0.152: v19.68,62.23 27.94,70.48 27.94,71.75 41.27,85.09 41.27,96.52 86.36,141.61 90.17,141.61 107.31,158.75 107.31,160.02 153.03,205.74 153.03,217.81 158.75,223.52 158.75,224.79 v160.66,226.69
  Bottom 0.152: v195.58,260.99 198.12,263.52 214,247.65 214.63,247.65 227.97,234.31 228.6,234.31 229.87,233.05 229.87,231.14 231.78,229.24 231.78,227.33 233.04,226.06 A14.U2
WCOV5  (via drill 0.61)
  Top 0.152: v152.4,289.56 151.76,290.19 142.88,290.19 130.81,278.13 123.83,278.13 84.45,238.76 81.28,238.76 A26.P2
  Route15 0.152: v152.4,289.56 168.28,289.56 168.91,288.92 179.07,288.92 200.03,267.97 206.38,267.97 215.26,259.08 219.07,259.08 220.34,257.81 A15.H2
WCOV6  (via drill 0.61)
  Top 0.152: v140.97,289.56 138.43,287.02 130.18,287.02 127,283.84 98.42,283.84 97.16,282.57 85.09,282.57 83.82,281.3 81.92,281.3 81.28,280.67 73.03,280.67 72.39,280.03 67.94,280.03 66.04,278.13 60.33,278.13 41.27,259.08 41.27,253.37 40.64,252.73 35.56,252.73 21.59,238.76 17.78,238.76 A31.P2
  Route15 0.152: v140.97,289.56 142.24,290.83 149.86,290.83 152.4,288.29 173.99,288.29 215.9,246.38 215.9,245.11 216.53,244.47 216.53,242.57 217.17,241.94 A15.N2

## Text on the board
Bottom: DM01 | VRS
